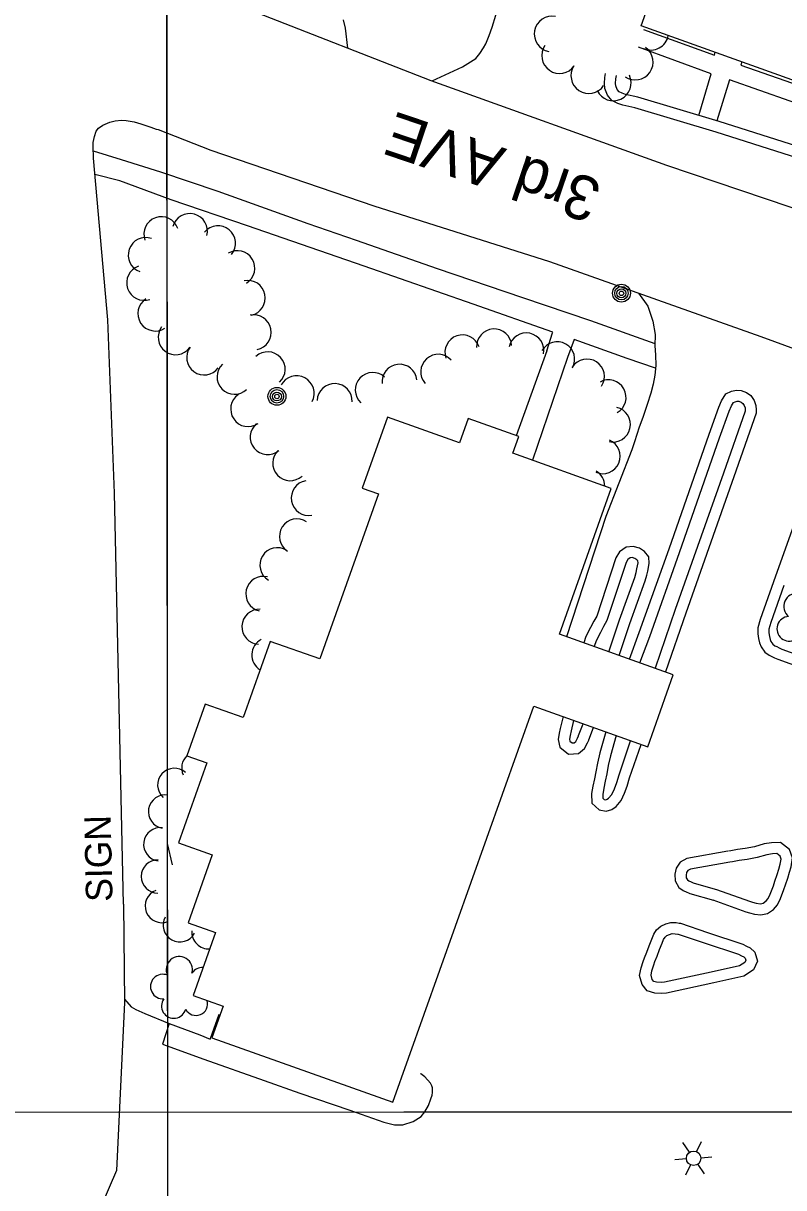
# Model space of a CAD drawing. Extents: x 189384 to 193282, y 256970 to 260388.
# Drawn here: x 191114.7 to 191286.7, y 257994.7 to 258258.1 of the extents above; entities that cross this region are included whole.
import ezdxf

# ---------------------------------------------------------------- set-up
doc = ezdxf.new("R2010")
doc.units = 0
for name, color, linetype in [('E_DWY', 7, 'Continuous'), ('E_LAND_Vegetation', 7, 'Continuous'), ('E_MAP_GridLines', 7, 'Continuous'), ('E_MISCPROP', 7, 'Continuous'), ('E_MISCPROP_HvyLine', 7, 'Continuous'), ('E_PATH_Sidewalk', 7, 'Continuous'), ('E_RDWY', 7, 'Continuous'), ('E_RDWY_Name', 7, 'Continuous')]:
    doc.layers.add(name, color=color, linetype=linetype)

# ---------------------------------------------------------------- blocks, each defined once
blk = doc.blocks.new('POLE_5')
at = {"layer": 'E_MISCPROP'}
for centre, radius in [((-0.01, 0.02), 2.02), ((-0.01, 0.03), 1.52), ((0, -0.01), 1.01), ((0, 0), 0.502)]:
    blk.add_circle(centre, radius, dxfattribs=at)
blk = doc.blocks.new('SIGN_3')
at = {"layer": 'E_MISCPROP'}
blk.add_text('SIGN', height=6, rotation=0.0001, dxfattribs=at).set_placement((-9.6, -3.01))
blk = doc.blocks.new('TREE_3')
at = {"layer": 'E_LAND_Vegetation'}
for centre, radius, start, end in [((-1.47, 4.28), 2.78, 1.3945, 209.1675), ((3.57, 2.42), 2.97, 278.4236, 139.6575), ((-4.47, 0.2), 2.78, 78.0715, 279.0825), ((-2.01, -4.2), 2.61, 140.7796, 358.7122), ((3.46, -3.43), 2.97, 196.0744, 79.0477)]:
    blk.add_arc(centre, radius, start, end, dxfattribs=at)
blk = doc.blocks.new('LTP_9')
at = {"layer": 'E_MISCPROP'}
for p, q in [((-0.8, 1.43), (-2, 3.73)), ((0.9, 1.42), (2.27, 3.65)), ((-1.64, 0.07), (-4.24, 0.14)), ((-0.88, -1.42), (-2.24, -3.61)), ((0.76, -1.47), (2, -3.65)), ((1.64, -0.02), (4.16, -0.09))]:
    blk.add_line(p, q, dxfattribs=at)
blk.add_circle((0, 0), 1.64, dxfattribs=at)

msp = doc.modelspace()

# ---------------------------------------------------------------- linework, layer by layer
at = {"layer": 'E_DWY'}
for points in [[(191207.15, 258245.04), (191214.03, 258248.26), (191217.02, 258250.14), (191217.96, 258251.27), (191218.81, 258252.56), (191219.29, 258253.47), (191220.05, 258255.34), (191220.74, 258257.19), (191221.55, 258259.91), (191222.51, 258263.1), (191223.15, 258265.19), (191223.86, 258267.63), (191224.42, 258269.66), (191225.41, 258273.25), (191226.93, 258278.13)], [(191188.13, 258252.45), (191187.59, 258257), (191187.1, 258258.88)], [(191341.51, 258222.01), (191340.41, 258219.15), (191339.22, 258216.96), (191338.02, 258215.24), (191336.64, 258214.17), (191335.07, 258213.8), (191333.76, 258213.67), (191332.05, 258213.85), (191330.97, 258214.32), (191306.68, 258222.23), (191271.37, 258233.47), (191253.02, 258238.97), (191250.27, 258239.59), (191249.17, 258239.93), (191247.84, 258240.6), (191246.83, 258241.85), (191246.23, 258243.35), (191246.14, 258244.47), (191246.24, 258245.85), (191246.38, 258246.71)], [(191339.18, 258222.91), (191338.14, 258220.2), (191337.09, 258218.28), (191336.19, 258216.99), (191335.53, 258216.48), (191334.65, 258216.27), (191333.76, 258216.18), (191332.69, 258216.3), (191331.85, 258216.66), (191307.44, 258224.61), (191272.11, 258235.86), (191253.66, 258241.39), (191250.92, 258242.01), (191250.11, 258242.26), (191249.45, 258242.59), (191249.02, 258243.13), (191248.69, 258243.94), (191248.65, 258244.48), (191248.73, 258245.55), (191248.85, 258246.31)], [(191253.82, 258197.08), (191255.92, 258194.14), (191257.06, 258190.68), (191257.58, 258187.68), (191257.55, 258185.12), (191257.64, 258183.11), (191257.79, 258180.67), (191257.5, 258178.47), (191257.14, 258176.5), (191256.62, 258174.45), (191255.81, 258171.84), (191254.79, 258168.92), (191254.02, 258166.75), (191252.94, 258163.45), (191252.32, 258161.63), (191246.43, 258146.53), (191237.52, 258119.35)], [(191251.79, 258114.27), (191254.02, 258120.27), (191260.76, 258139.23), (191269.79, 258165.18), (191272.02, 258171.29), (191272.58, 258172.66), (191273.56, 258174.31), (191274.88, 258174.89), (191275.96, 258175.13), (191277.07, 258175.06), (191278.22, 258174.59), (191279.2, 258173.9), (191279.95, 258172.77), (191280.38, 258171.67), (191280.47, 258170.68), (191280.43, 258169.89), (191275.4, 258155.52), (191264.51, 258124.64), (191259.96, 258111.36)], [(191254.14, 258113.43), (191256.37, 258119.42), (191263.12, 258138.4), (191272.14, 258164.34), (191274.35, 258170.39), (191274.83, 258171.54), (191275.3, 258172.34), (191275.66, 258172.5), (191276.16, 258172.61), (191276.5, 258172.59), (191277.02, 258172.38), (191277.39, 258172.12), (191277.72, 258171.62), (191277.92, 258171.1), (191277.96, 258170.63), (191277.95, 258170.37), (191273.04, 258156.35), (191262.14, 258125.46), (191257.61, 258112.2)], [(191293.45, 258157.33), (191284.33, 258131.73), (191281.35, 258123.27), (191280.84, 258121.38), (191280.81, 258120.02), (191280.97, 258118.92), (191281.18, 258117.98), (191281.57, 258117.02), (191282.42, 258115.84), (191283.37, 258115.17), (191283.98, 258114.85), (191284.62, 258114.55), (191285.32, 258114.23), (191319.59, 258101.91)], [(191249.49, 258115.09), (191251.88, 258122.32), (191255.36, 258131.96), (191255.7, 258133.24), (191255.92, 258134.19), (191256.24, 258135.92), (191256.14, 258137.43), (191255.2, 258138.61), (191254.08, 258139.35), (191252.6, 258139.77), (191251.06, 258139.57), (191249.57, 258138.56), (191248.74, 258137.2), (191244.38, 258124), (191243.73, 258122.83), (191242.99, 258121.45), (191241.96, 258119.37), (191241.45, 258117.95)], [(191247.13, 258115.93), (191249.52, 258123.14), (191252.97, 258132.7), (191253.28, 258133.84), (191253.47, 258134.7), (191253.73, 258136.06), (191253.7, 258136.48), (191253.48, 258136.75), (191253.03, 258137.05), (191252.42, 258137.22), (191251.97, 258137.16), (191251.42, 258136.79), (191251.02, 258136.14), (191246.69, 258122.99), (191245.92, 258121.62), (191245.21, 258120.3), (191244.26, 258118.39), (191243.8, 258117.11)], [(191286.69, 258130.9), (191283.74, 258122.53), (191283.33, 258121.02), (191283.31, 258120.18), (191283.43, 258119.38), (191283.58, 258118.73), (191283.78, 258118.24), (191284.21, 258117.64), (191284.68, 258117.3), (191285.09, 258117.09), (191285.65, 258116.83), (191286.26, 258116.55), (191320.44, 258104.26)], [(191236.77, 258101.26), (191236.15, 258098.59), (191235.9, 258097.49), (191235.69, 258096.1), (191236.05, 258094.39), (191237.98, 258092.76), (191240.24, 258092.91), (191241.59, 258094.03), (191242.33, 258095.32), (191242.57, 258095.96), (191242.59, 258096.01), (191243.65, 258098.81)], [(191239.14, 258100.41), (191238.59, 258098.02), (191238.36, 258097.02), (191238.23, 258096.17), (191238.32, 258095.75), (191238.82, 258095.32), (191239.27, 258095.35), (191239.65, 258095.67), (191240.06, 258096.39), (191240.27, 258096.95), (191240.3, 258097.01), (191241.29, 258099.64)], [(191246.45, 258097.81), (191245.07, 258093.04), (191244.56, 258090.72), (191244.21, 258088.8), (191243.85, 258087.16), (191243.53, 258085.53), (191243.24, 258083.84), (191243.25, 258081.66), (191244.94, 258080.21), (191246.56, 258079.91), (191247.83, 258080.29), (191248.76, 258080.9), (191249.95, 258082.31), (191250.7, 258083.96), (191251.3, 258085.54), (191251.83, 258087.39), (191254.4, 258094.98)], [(191248.81, 258096.97), (191247.5, 258092.42), (191247.01, 258090.22), (191246.66, 258088.31), (191246.3, 258086.65), (191245.99, 258085.07), (191245.74, 258083.63), (191245.74, 258082.82), (191246.06, 258082.55), (191246.42, 258082.48), (191246.77, 258082.58), (191247.08, 258082.79), (191247.82, 258083.66), (191248.39, 258084.92), (191248.93, 258086.33), (191249.44, 258088.13), (191252.05, 258095.82)], [(191274.02, 258070.82), (191264.75, 258069.15), (191263.24, 258068.33), (191262.38, 258067), (191262.07, 258065.64), (191262.12, 258064.09), (191262.98, 258062.65), (191263.95, 258061.91), (191264.77, 258061.57), (191265.15, 258061.41), (191265.46, 258061.25), (191270.78, 258059.74)], [(191270.62, 258059.79), (191278.1, 258057.12), (191278.96, 258056.85), (191280.03, 258056.61), (191281.49, 258056.41), (191282.99, 258056.72), (191284.38, 258057.67), (191285.3, 258058.71), (191285.95, 258060.12), (191286.7, 258062.19), (191287.05, 258063.22), (191287.57, 258064.76), (191287.96, 258066.07), (191288.32, 258067.3), (191288.66, 258069.3), (191287.96, 258071.18), (191285.96, 258072.82), (191283.87, 258072.75), (191282.28, 258072.47), (191280.08, 258071.82), (191277.98, 258071.43), (191276.2, 258071.19), (191274.7, 258070.91), (191274.17, 258070.84)], [(191274.47, 258068.36), (191265.59, 258066.76), (191265, 258066.44), (191264.72, 258066.01), (191264.58, 258065.39), (191264.6, 258064.82), (191264.88, 258064.35), (191265.21, 258064.09), (191265.74, 258063.88), (191266.23, 258063.66), (191266.39, 258063.58), (191271.45, 258062.15)], [(191271.45, 258062.15), (191278.9, 258059.49), (191279.61, 258059.27), (191280.47, 258059.07), (191281.4, 258058.95), (191281.99, 258059.07), (191282.71, 258059.56), (191283.18, 258060.1), (191283.64, 258061.08), (191284.34, 258063.02), (191284.68, 258064.02), (191285.19, 258065.52), (191285.56, 258066.78), (191285.88, 258067.87), (191286.08, 258069.05), (191285.85, 258069.68), (191285.1, 258070.29), (191284.13, 258070.26), (191282.85, 258070.03), (191280.67, 258069.39), (191278.38, 258068.96), (191276.6, 258068.72), (191275.08, 258068.43), (191274.47, 258068.36)], [(191270.83, 258041.03), (191260.13, 258038.73), (191259.04, 258038.62), (191257.49, 258038.71), (191255.79, 258039.22), (191254.66, 258040.68), (191254.09, 258042.73), (191254.45, 258044.45), (191254.92, 258045.9), (191255.22, 258046.72), (191255.71, 258047.98), (191256.28, 258049.45), (191256.84, 258050.92), (191257.27, 258052.04), (191257.94, 258053.02), (191258.88, 258053.87), (191260.02, 258054.37), (191261.16, 258054.69), (191262.34, 258054.67), (191263.04, 258054.55), (191263.34, 258054.51), (191269.47, 258052.47)], [(191270.3, 258043.48), (191259.73, 258041.2), (191258.99, 258041.12), (191257.93, 258041.19), (191257.28, 258041.38), (191256.94, 258041.83), (191256.66, 258042.81), (191256.87, 258043.8), (191257.29, 258045.09), (191257.56, 258045.84), (191258.04, 258047.07), (191258.61, 258048.56), (191259.17, 258050.03), (191259.49, 258050.87), (191259.84, 258051.37), (191260.26, 258051.75), (191260.86, 258052.01), (191261.48, 258052.18), (191262.11, 258052.17), (191262.69, 258052.07), (191262.79, 258052.06), (191268.68, 258050.1)], [(191269.47, 258052.47), (191277.44, 258049.82), (191278.27, 258049.38), (191279.06, 258048.99), (191280.16, 258047.96), (191280.73, 258045.95), (191279.83, 258043.98), (191277.67, 258042.54), (191270.84, 258041.03)], [(191268.68, 258050.1), (191276.46, 258047.51), (191277.13, 258047.16), (191277.62, 258046.91), (191277.95, 258046.61), (191278.07, 258046.15), (191277.85, 258045.66), (191276.67, 258044.88), (191270.3, 258043.48)], [(191137.58, 258037.36), (191139.12, 258035.62), (191140.21, 258034.98), (191142.18, 258034.13), (191147.74, 258031.86), (191146.19, 258027.16), (191155.57, 258023.76), (191169.19, 258018.96), (191177.29, 258016.11), (191188.58, 258012.22), (191196.25, 258009.5), (191198.63, 258008.91), (191200.52, 258008.95), (191202.86, 258009.67), (191204.7, 258010.81), (191205.49, 258011.88), (191206.34, 258013.34), (191206.89, 258014.8), (191207.18, 258015.66), (191207.29, 258016.22), (191207.27, 258017.33), (191207.11, 258017.74), (191206.77, 258018.33), (191205.5, 258019.82), (191204.6, 258020.44), (191204.51, 258020.47)]]:
    msp.add_lwpolyline(points, dxfattribs=at)
at = {"layer": 'E_LAND_Vegetation'}
for centre, radius, start, end in [((191234.3, 258255.66), 4.03, 79.0873, 259.0719), ((191256.61, 258256.07), 4.03, 246.3318, 349.3207), ((191235.99, 258250.78), 4.03, 145.2578, 325.2425), ((191253.1, 258249.31), 4.03, 234.9656, 54.9503), ((191242.6, 258246.23), 4.03, 146.2733, 326.258), ((191248.13, 258244.6), 4.03, 205.427, 25.4116), ((191145.95, 258210.37), 3.96, 19.7373, 199.722), ((191152.39, 258211.09), 3.96, 345.1685, 165.1532), ((191158.76, 258208.35), 3.96, 320.4771, 140.4617), ((191142.41, 258205.67), 3.96, 70.6384, 250.6231), ((191163.12, 258202.7), 3.96, 301.5362, 121.5209), ((191142.06, 258199.38), 3.96, 108.9717, 288.9564), ((191165.49, 258195.97), 3.96, 281.6147, 101.5994), ((191144.59, 258192.44), 3.96, 122.9164, 302.9011), ((191166.82, 258188.18), 3.96, 281.3449, 101.3296), ((191149.19, 258187.09), 3.96, 143.4289, 323.4136), ((191221.18, 258185), 3.96, 3.2534, 183.238), ((191214.03, 258183.65), 3.96, 18.9062, 198.8909), ((191228.48, 258184.1), 3.96, 348.264, 168.2487), ((191155.63, 258182.5), 3.96, 143.6384, 323.6231), ((191169.99, 258179.82), 3.96, 312.4987, 132.4834), ((191235.45, 258182.1), 3.96, 330.42, 150.4047), ((191162.49, 258178.13), 3.96, 133.7099, 313.6946), ((191208.54, 258179.26), 3.96, 41.8616, 221.8463), ((191242.18, 258178.18), 3.96, 326.9263, 146.911), ((191176.53, 258174.4), 3.96, 331.585, 151.5697), ((191193.74, 258175.15), 3.96, 47.2668, 227.2515), ((191199.79, 258177.01), 3.96, 5.9625, 185.9472), ((191185.13, 258172.64), 3.96, 357.8216, 177.8063), ((191247.07, 258173.49), 3.96, 299.2729, 119.2576), ((191165.58, 258170.82), 3.96, 124.1193, 304.104), ((191248.04, 258167.33), 3.96, 257.3243, 77.309), ((191170, 258164.49), 3.96, 129.6179, 309.6026), ((191245.72, 258160.18), 3.96, 246.9188, 66.9035), ((191175.08, 258158.59), 3.96, 132.9387, 312.9234), ((191242.26, 258153.37), 3.96, 0.8204, 59.4568), ((191179.28, 258150.72), 3.96, 100.2039, 280.1885), ((191176.6, 258142.02), 3.96, 56.897, 236.8817), ((191172.2, 258135.52), 3.96, 58.6678, 238.6525), ((191169, 258129.02), 3.96, 75.9888, 255.9735), ((191168.11, 258121.59), 3.96, 87.0399, 267.0245), ((191170.37, 258115.22), 3.96, 117.9826, 237.8526), ((191154.32, 258089.68), 3.78, 133.4874, 204.7277), ((191148.88, 258085.8), 3.78, 47.6848, 227.6695), ((191146.79, 258079.78), 3.78, 80.2294, 260.2141), ((191145.71, 258072.39), 3.78, 82.6598, 262.6445), ((191145.19, 258065.1), 3.78, 89.4513, 269.436), ((191146.06, 258058.43), 3.78, 111.3411, 291.3258), ((191150.14, 258054.09), 3.78, 150.8447, 330.8294), ((191156.61, 258052.51), 3.78, 175.5546, 274.55), ((191150.01, 258044.05), 2.97, 344.4507, 205.6846), ((191155.31, 258041.57), 2.97, 87.954, 145.0748), ((191146.27, 258040.2), 2.78, 67.4216, 275.1946), ((191148.77, 258035.8), 2.78, 144.0986, 345.1096), ((191153.79, 258036.27), 2.61, 206.8067, 17.35)]:
    msp.add_arc(centre, radius, start, end, dxfattribs=at)
at = {"layer": 'E_MAP_GridLines'}
for p, q in [((191147.76, 257511.81), (191146.69, 259011.8)), ((191148.11, 257011.81), (191147.05, 258511.8)), ((189647.41, 258010.74), (191647.4, 258012.16)), ((190147.4, 258011.09), (191647.4, 258012.16))]:
    msp.add_line(p, q, dxfattribs=at)
at = {"layer": 'E_MISCPROP'}
msp.add_line((191148.47, 258067.73), (191147.3, 258072.53), dxfattribs=at)
at = {"layer": 'E_MISCPROP_HvyLine'}
for points in [[(191284.9, 258335.94), (191363.96, 258307.6), (191335.59, 258228.44), (191254.45, 258257.52), (191262.46, 258279.88), (191264.54, 258279.13)], [(191198.26, 258014.04), (191230.14, 258103.61), (191255.91, 258094.44), (191261.7, 258110.74), (191235.94, 258119.91), (191247.68, 258152.9), (191225.43, 258160.82), (191226.77, 258164.6), (191215.29, 258168.69), (191213.34, 258163.19), (191197.05, 258168.99), (191191.35, 258152.96), (191195.05, 258151.64), (191181.76, 258114.3), (191170.54, 258118.29), (191164.41, 258101.06), (191155.87, 258104.1), (191151.71, 258092.42), (191156.26, 258090.8), (191149.82, 258072.73), (191157.45, 258070.01), (191151.98, 258054.64), (191158.22, 258052.42), (191153.15, 258038.16), (191159.94, 258035.74), (191157.39, 258028.58)]]:
    msp.add_lwpolyline(points, close=True, dxfattribs=at)
at = {"layer": 'E_PATH_Sidewalk'}
for points in [[(191255, 258256.66), (191270.99, 258250.86), (191271.15, 258251.54)], [(191267.47, 258237.25), (191270.23, 258246.63), (191253.86, 258252.66)], [(191277.17, 258249.38), (191276.96, 258248.59), (191313.49, 258235.89), (191313.61, 258236.32)], [(191339.18, 258222.91), (191301.87, 258235.66), (191274.41, 258245.34), (191271.52, 258236.04)], [(191130.56, 258229.22), (191136.89, 258227.28), (191145.73, 258224.5), (191158.73, 258220.11), (191179.05, 258212.79), (191189.98, 258209.01), (191208.31, 258202.59), (191227.63, 258196.06), (191243.01, 258190.88), (191257.56, 258185.68)], [(191233.12, 258184), (191234.38, 258188.05), (191234.43, 258188.2), (191216.42, 258194.56), (191191.82, 258203.15), (191165.39, 258212.26), (191148.18, 258218.16), (191136.53, 258222.48), (191130.9, 258223.92)], [(191257.71, 258180.1), (191251.3, 258182.29), (191239.26, 258186.56), (191237.8, 258182.5)], [(191233.12, 258184), (191226.2, 258164.81)], [(191237.8, 258182.5), (191229.86, 258159.25)], [(191147.74, 258031.86), (191154.66, 258029.25), (191156.97, 258028.29), (191157.08, 258028.44), (191159.02, 258033.95)]]:
    msp.add_lwpolyline(points, dxfattribs=at)
at = {"layer": 'E_RDWY'}
for points in [[(191364.67, 258189.73), (191350.69, 258194.53), (191320.2, 258205.24), (191293.68, 258214.61), (191260.24, 258225.93), (191206.95, 258245.11), (191166, 258261.09), (191139.89, 258270.02), (191123.72, 258276.54), (191122.11, 258292.57), (191117.18, 258342.51), (191116.85, 258347.51), (191116.97, 258348.34), (191135.27, 258400.42), (191152.49, 258450.05), (191152.52, 258450.16)], [(191137.39, 258058.86), (191135.34, 258151.8), (191133.82, 258191.01), (191130.58, 258227.58), (191130.55, 258230.27), (191130.54, 258231.14), (191130.81, 258232.46), (191131.23, 258233.67), (191131.77, 258234.38), (191132.74, 258235.05), (191134.3, 258235.7), (191135.54, 258236.05), (191136.91, 258236.17), (191138, 258236.1), (191139.82, 258235.82), (191141.32, 258235.37), (191142.67, 258234.89), (191143.54, 258234.59), (191144.17, 258234.39), (191144.79, 258234.18), (191145.19, 258234.09), (191157.11, 258229.4), (191194.01, 258216.78), (191233.68, 258204.23), (191281.46, 258187.27), (191300.67, 258180.26)], [(191137.39, 258058.86), (191137.59, 258036.63), (191135.8, 257998.58), (191124.74, 257972.86)]]:
    msp.add_lwpolyline(points, dxfattribs=at)

# ---------------------------------------------------------------- block references
at = {"layer": 'E_LAND_Vegetation', "rotation": 91.26356499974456}
msp.add_blockref('TREE_3', (191292.15, 258122.69), dxfattribs=at)
at = {"layer": 'E_MISCPROP'}
for name, p, rotation in [('POLE_5', (191249.98, 258197.02), -18.35509423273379), ('POLE_5', (191172.08, 258173.68), -18.355092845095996), ('SIGN_3', (191131.7, 258068.97), 91.26356785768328)]:
    msp.add_blockref(name, p, dxfattribs=dict(at, rotation=rotation))
at = {"layer": 'E_MISCPROP', "xscale": 1.0000015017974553, "yscale": 1.0000015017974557, "rotation": 66.23273793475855}
msp.add_blockref('LTP_9', (191266.3, 258001.36), dxfattribs=at)

# ---------------------------------------------------------------- texts
at = {"layer": 'E_RDWY_Name'}
msp.add_text('3rd AVE', height=10, rotation=161.2967, dxfattribs=at).set_placement((191246.01, 258222.24))

doc.saveas('drawing.dxf')
